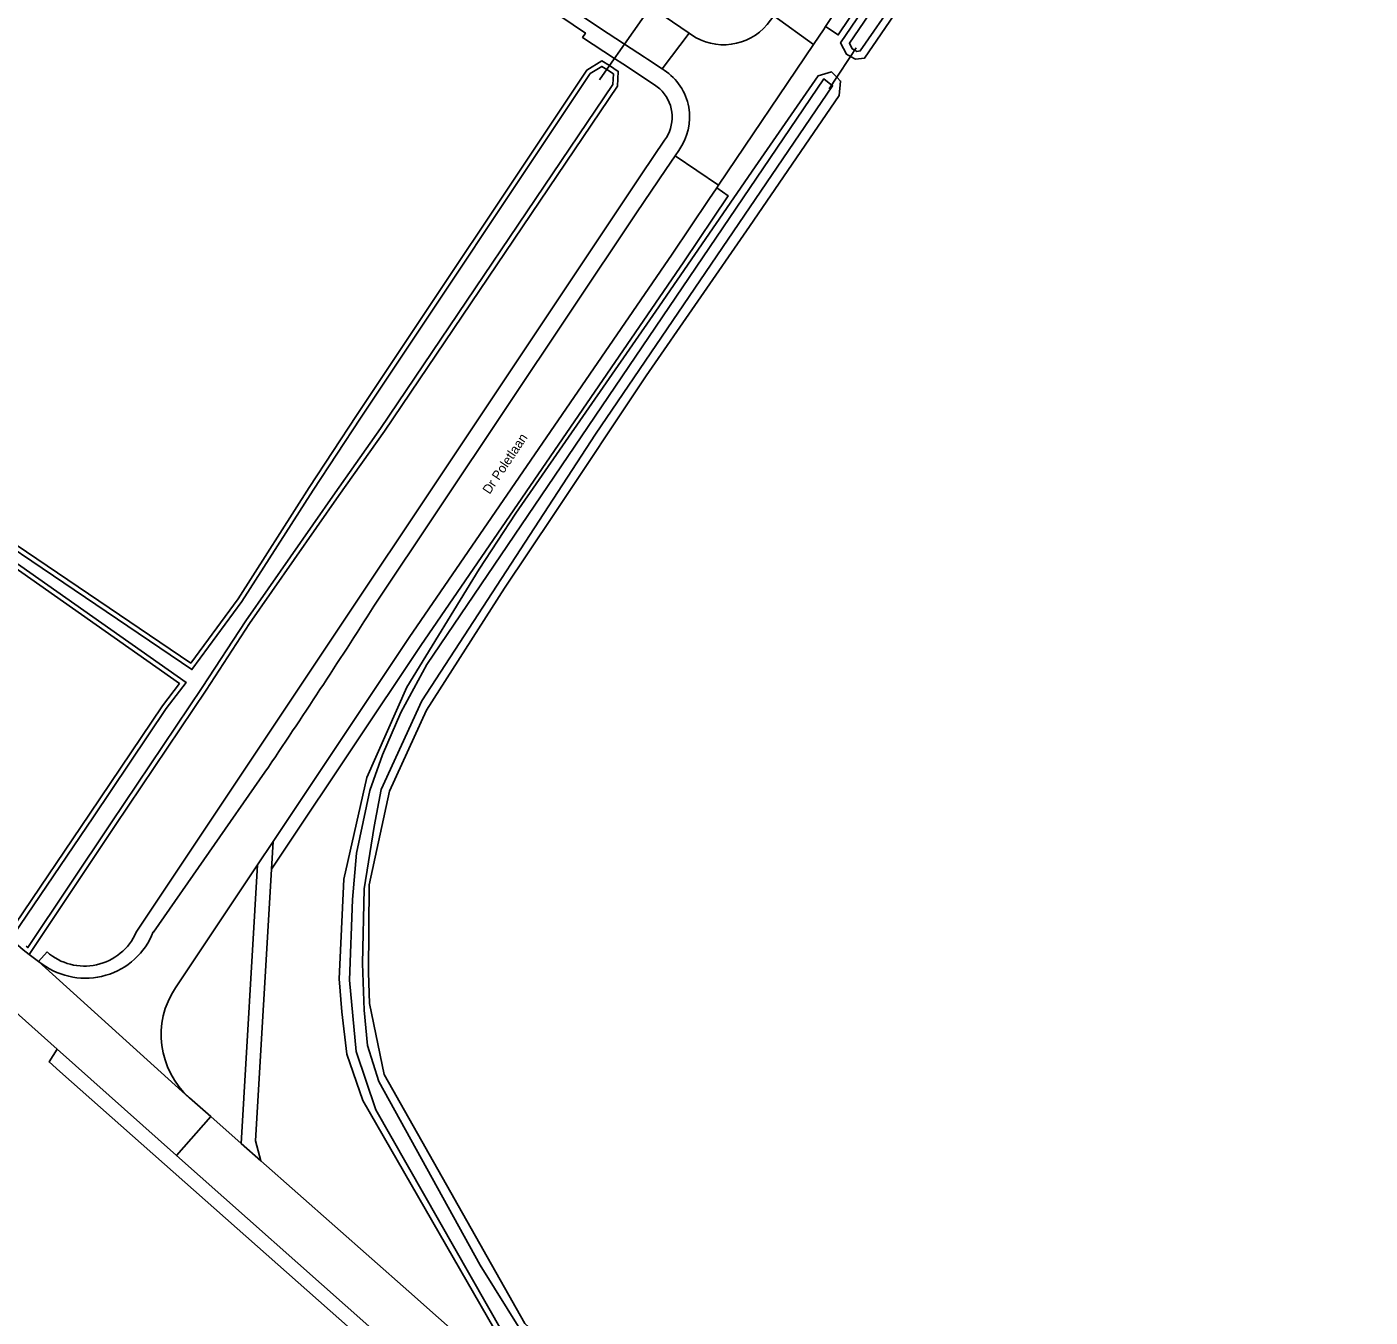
# Model space of a CAD drawing. Extents: x 158132 to 159664, y 385256 to 387218.
# Drawn here: x 159296.3 to 159439.3, y 385860.1 to 385997.5 of the extents above; entities that cross this region are included whole.
import ezdxf

# ---------------------------------------------------------------- set-up
doc = ezdxf.new("R2010")
doc.units = 0
for name, color, linetype in [('IMGEO_Berm_groen', 7, 'Continuous'), ('IMGEO_Duiker', 7, 'Continuous'), ('IMGEO_Fietspad_open', 7, 'Continuous'), ('IMGEO_Gemengd_bos', 7, 'Continuous'), ('IMGEO_Groenvoorziening', 7, 'Continuous'), ('IMGEO_Loofbos', 7, 'Continuous'), ('IMGEO_Oever', 7, 'Continuous'), ('IMGEO_Openbare_ruimte_label', 7, 'Continuous'), ('IMGEO_Parkeervlak_halfverhard', 7, 'Continuous'), ('IMGEO_Rijbaan_lokaal_gesloten', 7, 'Continuous'), ('IMGEO_Rijbaan_lokaal_open', 7, 'Continuous'), ('IMGEO_Voetpad_open', 7, 'Continuous'), ('IMGEO_Waterloop', 7, 'Continuous')]:
    doc.layers.add(name, color=color, linetype=linetype)

msp = doc.modelspace()

# ---------------------------------------------------------------- linework, layer by layer
at = {"layer": 'IMGEO_Berm_groen'}
msp.add_lwpolyline([(159369.74, 385980.34), (159368.91, 385979.1), (159365, 385973.3), (159337, 385932.46), (159322.51, 385910.76), (159322.34, 385907.8), (159323.76, 385909.93), (159338.24, 385931.62), (159366.24, 385972.46), (159370.97, 385979.48)], close=True, dxfattribs=at)
for points in [[(159320.85, 385908.28), (159312.11, 385895.18)], [(159313.62, 385883.46), (159315.86, 385881.48), (159319.11, 385878.6), (159320.85, 385908.28)]]:
    msp.add_lwpolyline(points, dxfattribs=at)
msp.add_arc((159319.59, 385890.18), 9, 146.2279, 228.3888, dxfattribs=at)
at = {"layer": 'IMGEO_Duiker'}
for points in [[(159364.38, 386002.06), (159363.53, 386000.84), (159362.95, 386000), (159362.67, 385999.6), (159359.91, 385995.65), (159358.31, 385993.36), (159357.26, 385991.85)], [(159381.7, 385990.88), (159382.52, 385992.13), (159383.99, 385994.33), (159384.59, 385995.24)]]:
    msp.add_lwpolyline(points, dxfattribs=at)
at = {"layer": 'IMGEO_Fietspad_open'}
msp.add_lwpolyline([(159358.33, 385836.48), (159332.7, 385859.13), (159312.23, 385877.33), (159299.53, 385888.62), (159298.65, 385887.27), (159299.79, 385886.27), (159344.98, 385846.27), (159357.19, 385835.22), (159370.76, 385823.15), (159373.58, 385820.69), (159421.75, 385777.33), (159428.81, 385771), (159432.59, 385767.85), (159434.84, 385765.65)], dxfattribs=at)
at = {"layer": 'IMGEO_Gemengd_bos'}
msp.add_lwpolyline([(159434.84, 385765.65), (159432.59, 385767.85), (159428.81, 385771), (159421.75, 385777.33), (159373.58, 385820.69), (159370.76, 385823.15), (159357.19, 385835.22), (159344.98, 385846.27), (159299.79, 385886.27), (159298.65, 385887.27), (159299.53, 385888.62), (159293.41, 385894.06), (159291.93, 385891.84), (159291.02, 385890.47), (159271.81, 385861.09), (159269.62, 385857.79), (159229.84, 385797.99), (159195.96, 385750), (159189.87, 385741.38), (159170.62, 385712.2), (159153.34, 385687.5)], dxfattribs=at)
at = {"layer": 'IMGEO_Groenvoorziening'}
for points in [[(159330.33, 386023.7), (159331.27, 386022.46), (159331.46, 386022.11), (159331.94, 386021.63), (159334.78, 386025.51), (159339.6, 386021.9), (159336.36, 386017.41), (159338.61, 386015.61), (159349.29, 386008.47), (159354.98, 386004.72), (159362.07, 386000), (159362.67, 385999.6), (159365, 385998.05), (159365.02, 385998.03), (159366.81, 385996.83), (159367.48, 385996.37)], [(159307.93, 385901.08), (159361.76, 385981.84), (159364.18, 385985.41), (159364.38, 385985.7), (159364.55, 385986.01), (159364.7, 385986.33), (159364.81, 385986.67), (159364.9, 385987.01), (159364.96, 385987.36), (159364.99, 385987.71), (159364.99, 385988.07), (159364.96, 385988.42), (159364.89, 385988.77), (159364.8, 385989.11), (159364.68, 385989.44), (159364.53, 385989.76), (159364.36, 385990.07), (159364.15, 385990.36), (159363.93, 385990.64), (159363.68, 385990.89), (159363.41, 385991.12), (159363.12, 385991.32), (159359.75, 385993.54), (159358.85, 385994.13), (159355.45, 385996.37), (159355.76, 385996.83), (159347.79, 386002.25)], [(159186.65, 385995.25), (159187.19, 385995.86), (159187.64, 385996.38), (159193.01, 385991.75), (159193.5, 385991.31), (159193.84, 385991.69), (159195.99, 385989.8), (159195.65, 385989.42), (159213.73, 385973.48), (159232.3, 385957.12), (159251.71, 385940.03), (159263.5, 385929.66), (159295.04, 385901.96), (159302.96, 385913.66), (159310.72, 385925.2), (159312.54, 385927.56), (159277.36, 385952.3), (159244.88, 385975.29)], [(159246.09, 385976.87), (159277.73, 385954.11), (159313.74, 385929.75), (159318.77, 385936.58), (159326.33, 385948.43), (159331.4, 385956.1), (159355.92, 385992.89), (159357.52, 385993.86), (159358.31, 385993.36), (159359.26, 385992.74), (159359.16, 385991.19), (159334.35, 385954.45), (159329.51, 385947.59), (159320.01, 385933.95), (159315.38, 385926.85), (159305.68, 385912.46), (159296.52, 385898.73), (159297.54, 385897.96), (159298.44, 385898.99)]]:
    msp.add_lwpolyline(points, dxfattribs=at)
for centre, radius, start, end in [((159370.47, 386001.66), 6.08, 240.5287, 325.3494), ((159302.42, 385903.49), 6.01, 228.5204, 336.4067)]:
    msp.add_arc(centre, radius, start, end, dxfattribs=at)
at = {"layer": 'IMGEO_Loofbos'}
msp.add_lwpolyline([(159395.39, 386008.63), (159389.48, 386000), (159385.48, 385994.17), (159384.51, 385994.05), (159383.99, 385994.33), (159383.56, 385994.57), (159382.93, 385995.79), (159385.79, 386000), (159393.1, 386010.75), (159408.76, 386034.08), (159422.33, 386053.78), (159431.59, 386068.19), (159433.03, 386069.16), (159433.99, 386068.57), (159434, 386066.48), (159423.66, 386050.6), (159412.31, 386033.82)], close=True, dxfattribs=at)
for points in [[(159422.73, 386058.55), (159423.83, 386057.81), (159382.67, 385996.63), (159381.32, 385997.52), (159381.21, 385997.35), (159381.17, 385997.29), (159380.03, 385995.6), (159369.94, 385980.63), (159369.74, 385980.34), (159370.97, 385979.48), (159366.24, 385972.46), (159338.24, 385931.62), (159323.76, 385909.93), (159322.34, 385907.8), (159320.63, 385878.88), (159321.2, 385876.76), (159336.97, 385862.82), (159375.8, 385828.33), (159378.77, 385825.67), (159417.87, 385790.77), (159418.01, 385790.94), (159418.04, 385790.91), (159419.79, 385789.39)], [(159346.82, 385857.51), (159332.05, 385883.18), (159330.37, 385888.12), (159329.82, 385892.62), (159329.54, 385896.14), (159330.03, 385906.73), (159332.47, 385917.55), (159336.73, 385927.18), (159344.46, 385939.76), (159348.34, 385945.7), (159363.26, 385967.23), (159373.82, 385982.57), (159380.53, 385992.28), (159381.94, 385992.69), (159382.52, 385992.13), (159382.93, 385991.72), (159382.77, 385990.18), (159373.21, 385976.23), (159362.22, 385960.32), (159352.38, 385945.57), (159347.15, 385937.71), (159338.84, 385924.72), (159334.9, 385916.12), (159332.73, 385906.12), (159332.66, 385896.81), (159332.78, 385893.49), (159334.32, 385885.93), (159349.29, 385859.41)]]:
    msp.add_lwpolyline(points, dxfattribs=at)
at = {"layer": 'IMGEO_Oever'}
for points in [[(159423.66, 386050.6), (159434, 386066.48), (159433.99, 386068.57), (159433.03, 386069.16), (159431.59, 386068.19), (159422.33, 386053.78), (159408.76, 386034.08), (159393.1, 386010.75), (159385.79, 386000), (159382.93, 385995.79), (159383.56, 385994.57), (159383.99, 385994.33), (159384.51, 385994.05), (159385.48, 385994.17), (159389.48, 386000), (159395.39, 386008.63), (159412.31, 386033.82)], [(159384.37, 385995.04), (159384.16, 385995.15), (159383.86, 385995.74), (159386.45, 385999.55), (159393.76, 386010.3), (159409.42, 386033.63), (159423, 386053.34), (159432.17, 386067.61), (159433.05, 386068.2), (159433.19, 386068.12), (159433.2, 386066.71), (159422.99, 386051.04), (159411.64, 386034.26), (159394.73, 386009.08), (159388.81, 386000.45), (159385.02, 385994.92), (159384.66, 385994.88), (159384.43, 385995.01)]]:
    msp.add_lwpolyline(points, close=True, dxfattribs=at)
for points in [[(159359.16, 385991.19), (159359.26, 385992.74), (159358.31, 385993.36), (159357.52, 385993.86), (159355.92, 385992.89), (159331.4, 385956.1), (159326.33, 385948.43), (159318.77, 385936.58), (159313.74, 385929.75), (159277.73, 385954.11), (159246.09, 385976.87)], [(159277.45, 385953.7), (159313.86, 385929.06), (159319.19, 385936.3), (159326.76, 385948.15), (159331.82, 385955.82), (159356.28, 385992.52), (159357.51, 385993.27), (159358.02, 385992.94), (159358.74, 385992.48), (159358.67, 385991.36), (159333.93, 385954.74), (159329.1, 385947.88), (159319.6, 385934.23), (159314.96, 385927.13), (159305.26, 385912.74), (159296.4, 385899.46), (159296.21, 385899.61)], [(159362.22, 385960.32), (159373.21, 385976.23), (159382.77, 385990.18), (159382.93, 385991.72), (159382.52, 385992.13), (159381.94, 385992.69), (159380.53, 385992.28), (159373.82, 385982.57), (159363.26, 385967.23), (159348.34, 385945.7), (159344.46, 385939.76), (159336.73, 385927.18), (159332.47, 385917.55), (159330.03, 385906.73), (159329.54, 385896.14), (159329.82, 385892.62), (159330.37, 385888.12), (159332.05, 385883.18), (159346.82, 385857.51), (159376.18, 385831.42), (159391.38, 385818.18), (159396.24, 385813.5), (159421.84, 385790.96)], [(159346.93, 385858.51), (159333.43, 385882.16), (159331.36, 385888.39), (159330.63, 385896), (159330.97, 385904.58), (159331.39, 385909.5), (159332.79, 385916.17), (159334.15, 385919.99), (159336.11, 385924.49), (159338.86, 385929.59), (159381.14, 385991.94), (159382.08, 385991.22), (159356.82, 385954.11), (159338.34, 385925.74), (159334.01, 385916.28), (159333.25, 385912.33), (159332.19, 385905.7), (159332.02, 385897.76), (159332.19, 385892.79), (159332.57, 385889.01), (159333.76, 385885.19), (159344.54, 385865.62), (159348.96, 385858.57)], [(159244.88, 385975.29), (159277.36, 385952.3), (159312.54, 385927.56), (159310.72, 385925.2), (159302.96, 385913.66), (159295.04, 385901.96), (159294.2, 385900.72), (159294.52, 385900.43), (159295.89, 385899.22), (159296.52, 385898.73), (159305.68, 385912.46), (159315.38, 385926.85), (159320.01, 385933.95), (159329.51, 385947.59), (159334.35, 385954.45), (159359.16, 385991.19)], [(159439.3, 385818.41), (159422.24, 385794.37), (159397.53, 385815.84), (159392.98, 385819.98), (159377.52, 385833.49), (159349.29, 385859.41), (159334.32, 385885.93), (159332.78, 385893.49), (159332.66, 385896.81), (159332.73, 385906.12), (159334.9, 385916.12), (159338.84, 385924.72), (159347.15, 385937.71), (159352.38, 385945.57), (159362.22, 385960.32)], [(159294.87, 385900.8), (159303.37, 385913.38), (159311.13, 385924.9), (159313.26, 385927.67), (159277.66, 385952.71)]]:
    msp.add_lwpolyline(points, dxfattribs=at)
at = {"layer": 'IMGEO_Parkeervlak_halfverhard'}
msp.add_lwpolyline([(159421.5, 386056.95), (159404.94, 386032.53), (159382.99, 386000), (159381.32, 385997.52), (159382.67, 385996.63), (159423.83, 386057.81), (159422.73, 386058.55)], dxfattribs=at)
at = {"layer": 'IMGEO_Rijbaan_lokaal_gesloten'}
for points in [[(159420.26, 386064.31), (159416.73, 386059.02), (159412.72, 386053.02), (159408.2, 386046.25), (159404.16, 386040.2), (159400.94, 386035.39), (159399.91, 386033.87), (159395.86, 386027.92), (159391.19, 386021.07), (159380.36, 386005.18), (159378.77, 386002.85), (159377.37, 386000.8), (159376.97, 386000.22), (159376.94, 386000.17), (159376.81, 386000), (159375.8, 385998.65), (159380.03, 385995.6), (159381.17, 385997.29), (159381.21, 385997.35), (159381.32, 385997.52), (159382.99, 386000), (159404.94, 386032.53), (159421.5, 386056.95)], [(159338.45, 386009.93), (159345.38, 386005.36), (159348.48, 386003.28), (159353.37, 386000), (159357.27, 385997.38), (159359.91, 385995.65), (159362.06, 385994.25), (159362.35, 385994.06), (159363.93, 385993.02), (159366.81, 385996.83), (159365.02, 385998.03), (159365, 385998.05), (159362.67, 385999.6), (159362.07, 386000), (159354.98, 386004.72), (159349.29, 386008.47), (159338.61, 386015.61), (159336.36, 386017.41), (159335.91, 386017.76), (159331.94, 386021.63), (159331.46, 386022.11), (159331.27, 386022.46), (159330.33, 386023.7)], [(159365, 385973.3), (159368.91, 385979.1), (159369.74, 385980.34), (159369.94, 385980.63), (159365.31, 385983.76), (159364.33, 385982.31), (159361.2, 385977.7), (159333.23, 385935.8)], [(159312.11, 385895.18), (159320.85, 385908.28), (159322.51, 385910.76), (159337, 385932.46), (159365, 385973.3)], [(159321.64, 385918.13), (159309.76, 385901.11)], [(159297.93, 385897.67), (159297.54, 385897.96), (159313.57, 385883.46), (159313.62, 385883.46)]]:
    msp.add_lwpolyline(points, dxfattribs=at)
for points in [[(159297.54, 385897.96), (159296.52, 385898.73), (159295.89, 385899.22), (159294.52, 385900.43), (159291.04, 385896.17), (159291.09, 385896.12), (159293.41, 385894.06), (159299.53, 385888.62), (159312.23, 385877.33), (159315.86, 385881.48), (159313.62, 385883.46), (159313.57, 385883.46)], [(159336.97, 385862.82), (159321.2, 385876.76), (159319.11, 385878.6), (159315.86, 385881.48), (159312.23, 385877.33), (159332.7, 385859.13), (159358.33, 385836.48), (159371.86, 385824.45), (159374.77, 385821.88), (159414.14, 385786.45), (159414.24, 385786.36), (159418.04, 385790.91), (159418.01, 385790.94), (159417.87, 385790.77), (159378.77, 385825.67), (159375.8, 385828.33)]]:
    msp.add_lwpolyline(points, close=True, dxfattribs=at)
for centre, radius, start, end in [((158703.05, 386336.47), 746.77, 325.93016, 327.55151), ((159302.51, 385903.98), 7.79, 234.0313, 338.4243), ((159319.59, 385890.18), 9, 146.2279, 228.3888)]:
    msp.add_arc(centre, radius, start, end, dxfattribs=at)
at = {"layer": 'IMGEO_Rijbaan_lokaal_open'}
for points in [[(159380.03, 385995.6), (159375.8, 385998.65), (159375.46, 385998.21)], [(159367.48, 385996.37), (159366.81, 385996.83), (159363.93, 385993.02), (159364.14, 385992.88)], [(159365.7, 385984.33), (159365.31, 385983.76), (159369.94, 385980.63), (159380.03, 385995.6)]]:
    msp.add_lwpolyline(points, dxfattribs=at)
for centre, radius, start, end in [((159370.47, 386001.66), 6.08, 240.5287, 325.3494), ((159360.87, 385987.87), 5.98, 323.7316, 56.858)]:
    msp.add_arc(centre, radius, start, end, dxfattribs=at)
at = {"layer": 'IMGEO_Voetpad_open'}
for points in [[(159347.79, 386002.25), (159355.76, 385996.83), (159355.45, 385996.37), (159358.85, 385994.13), (159359.75, 385993.54), (159363.12, 385991.32), (159363.41, 385991.12), (159363.68, 385990.89), (159363.93, 385990.64), (159364.15, 385990.36), (159364.36, 385990.07), (159364.53, 385989.76), (159364.68, 385989.44), (159364.8, 385989.11), (159364.89, 385988.77), (159364.96, 385988.42), (159364.99, 385988.07), (159364.99, 385987.71), (159364.96, 385987.36), (159364.9, 385987.01), (159364.81, 385986.67), (159364.7, 385986.33), (159364.55, 385986.01), (159364.38, 385985.7), (159364.18, 385985.41), (159361.76, 385981.84), (159307.93, 385901.08)], [(159357.27, 385997.38), (159353.37, 386000)], [(159364.14, 385992.88), (159363.93, 385993.02), (159362.35, 385994.06), (159362.06, 385994.25), (159359.91, 385995.65), (159357.27, 385997.38)], [(159333.23, 385935.8), (159361.2, 385977.7), (159364.33, 385982.31), (159365.31, 385983.76), (159365.7, 385984.33)], [(159309.76, 385901.11), (159321.64, 385918.13)], [(159298.44, 385898.99), (159297.54, 385897.96), (159297.93, 385897.67)]]:
    msp.add_lwpolyline(points, dxfattribs=at)
msp.add_lwpolyline([(159322.34, 385907.8), (159322.51, 385910.76), (159320.85, 385908.28), (159319.11, 385878.6), (159321.2, 385876.76), (159320.63, 385878.88)], close=True, dxfattribs=at)
for centre, radius, start, end in [((159360.87, 385987.87), 5.98, 323.7316, 56.858), ((158703.05, 386336.47), 746.77, 325.93016, 327.55151), ((159302.51, 385903.98), 7.79, 234.0313, 338.4243), ((159302.42, 385903.49), 6.01, 228.5204, 336.4067)]:
    msp.add_arc(centre, radius, start, end, dxfattribs=at)
at = {"layer": 'IMGEO_Waterloop'}
msp.add_lwpolyline([(159384.37, 385995.04), (159384.43, 385995.01), (159384.66, 385994.88), (159385.02, 385994.92), (159388.81, 386000.45), (159394.73, 386009.08), (159411.64, 386034.26), (159422.99, 386051.04), (159433.2, 386066.71), (159433.19, 386068.12), (159433.05, 386068.2), (159432.17, 386067.61), (159423, 386053.34), (159409.42, 386033.63), (159393.76, 386010.3), (159386.45, 385999.55), (159383.86, 385995.74), (159384.16, 385995.15)], close=True, dxfattribs=at)
for points in [[(159296.21, 385899.61), (159296.4, 385899.46), (159305.26, 385912.74), (159314.96, 385927.13), (159319.6, 385934.23), (159329.1, 385947.88), (159333.93, 385954.74), (159358.67, 385991.36), (159358.74, 385992.48), (159358.02, 385992.94), (159357.51, 385993.27), (159356.28, 385992.52), (159331.82, 385955.82), (159326.76, 385948.15), (159319.19, 385936.3), (159313.86, 385929.06), (159277.45, 385953.7)], [(159348.96, 385858.57), (159344.54, 385865.62), (159333.76, 385885.19), (159332.57, 385889.01), (159332.19, 385892.79), (159332.02, 385897.76), (159332.19, 385905.7), (159333.25, 385912.33), (159334.01, 385916.28), (159338.34, 385925.74), (159356.82, 385954.11), (159382.08, 385991.22), (159381.14, 385991.94), (159338.86, 385929.59), (159336.11, 385924.49), (159334.15, 385919.99), (159332.79, 385916.17), (159331.39, 385909.5), (159330.97, 385904.58), (159330.63, 385896), (159331.36, 385888.39), (159333.43, 385882.16), (159346.93, 385858.51)], [(159277.66, 385952.71), (159313.26, 385927.67), (159311.13, 385924.9), (159303.37, 385913.38), (159294.87, 385900.8)]]:
    msp.add_lwpolyline(points, dxfattribs=at)

# ---------------------------------------------------------------- texts
at = {"layer": 'IMGEO_Openbare_ruimte_label'}
msp.add_text('Dr Poletlaan', height=1, rotation=56.294, dxfattribs=at).set_placement((159345.56, 385947.65))

doc.saveas('drawing.dxf')
